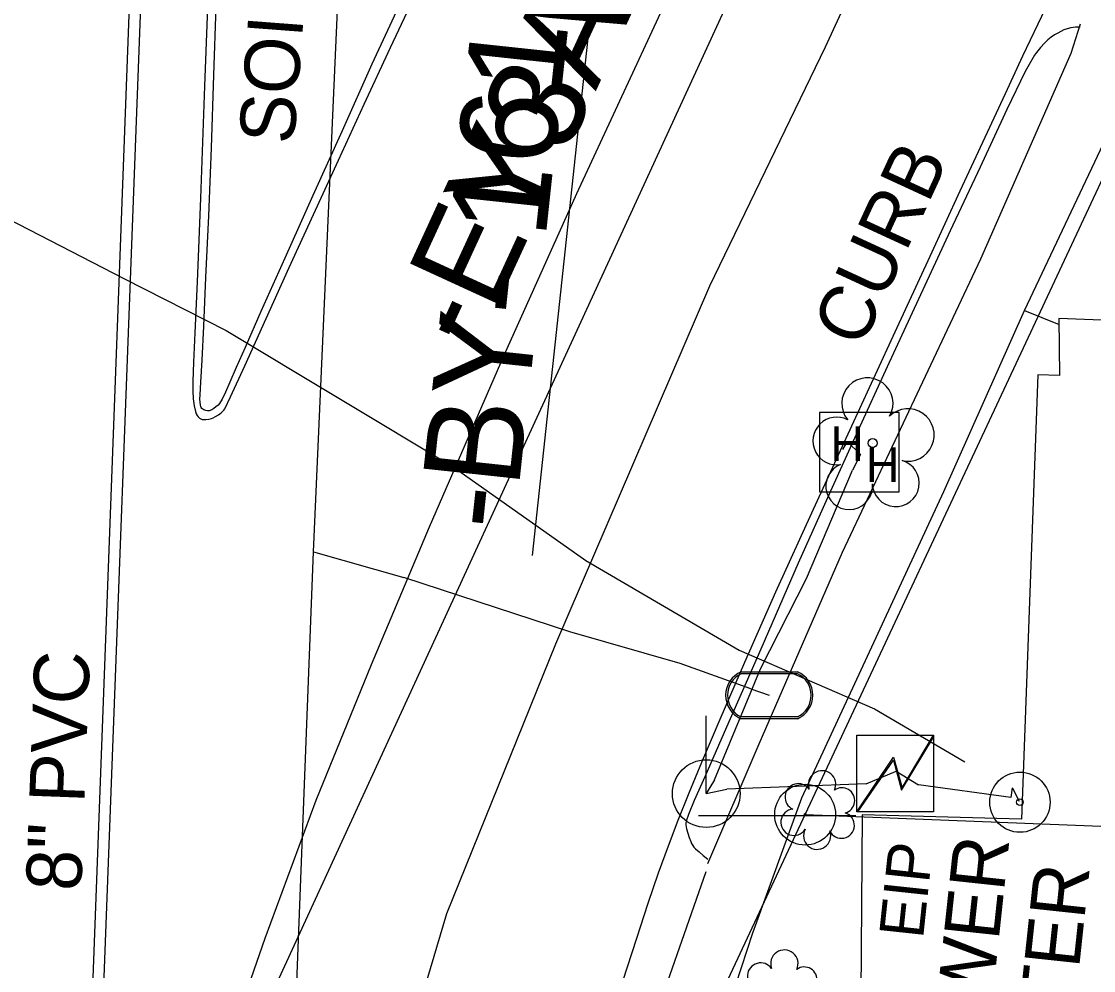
# Model space of a CAD drawing. Extents: x 2100323 to 2109811, y 740376 to 749755.
# Drawn here: x 2105116.4 to 2105194, y 742002.8 to 742071.5 of the extents above; entities that cross this region are included whole.
import ezdxf

# ---------------------------------------------------------------- set-up
doc = ezdxf.new("R2010")
doc.units = 0
for name, color, linetype in [('Exist Building', 7, 'Continuous'), ('Exist Horizontal Alignment', 7, 'Continuous'), ('Exist Horizontal Alignment Direction Label', 7, 'Continuous'), ('Exist Horizontal Baseline Alignment Station Label', 7, 'Continuous'), ('Exist Property Iron Pin CELL', 7, 'Continuous'), ('Exist Property Iron Pin Text', 7, 'Continuous'), ('Exist Property Line', 7, 'Continuous'), ('Exist Right of Way Line', 7, 'Continuous'), ('Exist Roads Curbs', 7, 'Continuous'), ('Exist Roads Curbs Text', 7, 'Continuous'), ('Exist Roads EOP', 7, 'Continuous'), ('Exist Roads EOP Other', 7, 'Continuous'), ('Exist Roads EOP Other Text', 7, 'Continuous'), ('Exist Roads EOT', 7, 'Continuous'), ('Exist Utilities Other Located Object CELL', 7, 'Continuous'), ('Exist Utilities Other Located Object Text', 7, 'Continuous'), ('Exist Utilities Power Hand Hole CELL', 7, 'Continuous'), ('Exist Utilities Power Pole CELL', 7, 'Continuous'), ('Exist Utilities Power Transformer CELL', 7, 'Continuous'), ('Exist Utilities Power UG Cable SUE LOS B', 7, 'Continuous'), ('Exist Utilities Sanitary Sewer UG Line', 7, 'Continuous'), ('Exist Utilities Sanitary Sewer UG Line Text', 7, 'Continuous'), ('Exist Utilities Telephone UG Conduit SUE LOS B', 7, 'Continuous'), ('Exist Utilities TV UG Cable SUE LOS B', 7, 'Continuous'), ('Exist Utilities Water Meter CELL', 7, 'Continuous'), ('Exist Utilities Water UG Line SUE LOS B', 7, 'Continuous'), ('Exist Vegetation Shrub CELL', 7, 'Continuous'), ('Exist Vegetation Tree CELL', 7, 'Continuous')]:
    doc.layers.add(name, color=color, linetype=linetype)

msp = doc.modelspace()

# ---------------------------------------------------------------- linework, layer by layer
at = {"layer": 'Exist Building'}
msp.add_lwpolyline([(2105393.559, 742042.638), (2105393.942, 742090.402), (2105372.247, 742090.309), (2105372.364, 742094.565), (2105338.596, 742094.683), (2105338.145, 742078.613), (2105341.859, 742078.569), (2105341.416, 742009.009), (2105288.421, 742009.568), (2105292.363, 742046.053), (2105191.496, 742049.965), (2105191.549, 742045.846), (2105189.964, 742045.895), (2105188.785, 742013.721), (2105177.253, 742014.042), (2105176.911, 741968.504), (2105222.955, 741968.258), (2105222.207, 741851.808), (2105348.078, 741851.227), (2105349.033, 742009.047), (2105393.054, 742008.763)], dxfattribs=at)
at = {"layer": 'Exist Horizontal Alignment'}
for p, q in [((2105114.07, 741782.467), (2105127.955, 742149.664)), ((2105121.244, 741972.172), (2105202.941, 742149.867))]:
    msp.add_line(p, q, dxfattribs=at)
at = {"layer": 'Exist Horizontal Baseline Alignment Station Label'}
msp.add_line((2105158.033, 742076.269), (2105153.379, 742032.816), dxfattribs=at)
at = {"layer": 'Exist Property Iron Pin CELL'}
for radius in [2.203, 0.0707]:
    msp.add_circle((2105173.125, 742014.049), radius, dxfattribs=at)
at = {"layer": 'Exist Property Line'}
msp.add_line((2105173.125, 742014.049), (2105289.481, 742009.548), dxfattribs=at)
at = {"layer": 'Exist Right of Way Line'}
msp.add_line((2105154.33, 741973.823), (2105222.691, 742120.13), dxfattribs=at)
at = {"layer": 'Exist Roads Curbs'}
for points in [[(2105144.025, 742073.29), (2105141.774, 742068.401), (2105139.603, 742063.573), (2105137.499, 742058.879), (2105135.46, 742054.333), (2105133.738, 742050.485), (2105132.584, 742047.886), (2105131.943, 742046.418), (2105131.489, 742045.373), (2105131.167, 742044.634), (2105130.929, 742044.135), (2105130.725, 742043.809), (2105130.636, 742043.711), (2105130.474, 742043.571), (2105130.324, 742043.455), (2105130.186, 742043.364), (2105130.12, 742043.332), (2105130.056, 742043.308), (2105129.993, 742043.294), (2105129.932, 742043.289), (2105129.87, 742043.291), (2105129.738, 742043.315), (2105129.593, 742043.363), (2105129.523, 742043.401), (2105129.464, 742043.453), (2105129.417, 742043.52), (2105129.382, 742043.601), (2105129.358, 742043.697), (2105129.331, 742043.909), (2105129.324, 742044.133), (2105129.338, 742044.452), (2105129.386, 742045.369), (2105129.471, 742046.968), (2105129.593, 742049.431), (2105129.757, 742052.941), (2105129.954, 742057.41), (2105130.149, 742062.324), (2105130.335, 742067.596), (2105130.506, 742072.573)], [(2105193.026, 742071.079), (2105192.693, 742071.065), (2105192.356, 742071.023), (2105192.099, 742070.957), (2105191.86, 742070.871), (2105191.632, 742070.765), (2105191.406, 742070.642), (2105191.176, 742070.506), (2105190.942, 742070.352), (2105190.697, 742070.153), (2105190.44, 742069.904), (2105190.166, 742069.602), (2105189.871, 742069.248), (2105189.716, 742069.05), (2105189.062, 742067.859), (2105187.73, 742065.104), (2105185.787, 742060.942), (2105183.635, 742056.315), (2105181.34, 742051.381), (2105179.062, 742046.464), (2105176.958, 742041.887), (2105174.957, 742037.483), (2105172.631, 742032.256), (2105169.909, 742026.042), (2105167.437, 742020.373), (2105165.862, 742016.784), (2105165.102, 742015.077), (2105164.679, 742014.07), (2105164.511, 742013.564), (2105164.498, 742013.434), (2105164.498, 742013.298), (2105164.538, 742013.011), (2105164.626, 742012.705), (2105164.73, 742012.402), (2105164.842, 742012.104), (2105164.908, 742011.961), (2105164.988, 742011.825), (2105165.081, 742011.696), (2105165.189, 742011.574), (2105165.444, 742011.346), (2105165.739, 742011.098), (2105166.072, 742010.821)]]:
    msp.add_lwpolyline(points, dxfattribs=at)
at = {"layer": 'Exist Roads EOP'}
for points in [[(2105195.1, 742082.43), (2105193.599, 742079.111), (2105192.261, 742076.186), (2105191.054, 742073.583), (2105189.972, 742071.292), (2105188.869, 742068.964), (2105187.598, 742066.249), (2105186.133, 742063.094), (2105184.323, 742059.185), (2105182.142, 742054.469), (2105179.615, 742048.996), (2105176.768, 742042.817), (2105173.698, 742036.133), (2105170.991, 742030.147), (2105168.744, 742025.059), (2105166.957, 742020.929), (2105165.629, 742017.817), (2105164.71, 742015.61), (2105163.916, 742013.628), (2105163.2, 742011.758), (2105162.495, 742009.812), (2105161.739, 742007.605), (2105160.912, 742005.087), (2105159.909, 742001.961)], [(2105129.963, 742075.061), (2105129.653, 742066.796), (2105129.352, 742058.682), (2105129.116, 742052.622), (2105128.956, 742048.932), (2105128.858, 742046.804), (2105128.808, 742045.425), (2105128.804, 742044.712), (2105128.834, 742044.148), (2105128.897, 742043.648), (2105128.993, 742043.239), (2105129.054, 742043.079), (2105129.123, 742042.948), (2105129.2, 742042.846), (2105129.287, 742042.769), (2105129.384, 742042.711), (2105129.491, 742042.673), (2105129.608, 742042.654), (2105129.735, 742042.655), (2105129.97, 742042.683), (2105130.147, 742042.726), (2105130.278, 742042.786), (2105130.442, 742042.875), (2105130.653, 742042.995), (2105130.765, 742043.066), (2105130.867, 742043.146), (2105130.959, 742043.232), (2105131.041, 742043.327), (2105131.113, 742043.429), (2105131.542, 742044.314), (2105132.56, 742046.544), (2105134.103, 742049.967), (2105135.781, 742053.669), (2105137.529, 742057.497), (2105139.342, 742061.443), (2105141.214, 742065.496), (2105143.12, 742069.606), (2105144.914, 742073.465)]]:
    msp.add_lwpolyline(points, dxfattribs=at)
at = {"layer": 'Exist Roads EOP Other'}
for points in [[(2105188.998, 742050.567), (2105195.555, 742064.436), (2105200.254, 742074.54), (2105206.049, 742087.143), (2105212.074, 742100.512)], [(2105166.081, 742010.498), (2105169.81, 742019.172), (2105175.83, 742033.05), (2105185.844, 742054.299), (2105192.373, 742069.189), (2105193.061, 742071.322)], [(2105164.824, 741991.679), (2105169.348, 742005.482), (2105172.881, 742015.259), (2105183.158, 742037.456), (2105188.998, 742050.567), (2105191.502, 742049.546)], [(2105147.385, 741940.48), (2105150.205, 741954.812), (2105153.355, 741968.426), (2105158.258, 741986.568), (2105161.606, 741997.427), (2105165.959, 742009.922)]]:
    msp.add_lwpolyline(points, dxfattribs=at)
at = {"layer": 'Exist Roads EOT'}
for points in [[(2105182.093, 742112.636), (2105177.783, 742103.921), (2105172.174, 742092.295), (2105168.421, 742084.389), (2105162.799, 742072.415), (2105156.586, 742059.006), (2105151.308, 742047.303), (2105145.911, 742034.869), (2105141.71, 742024.904), (2105137.709, 742015.074), (2105134.028, 742005.078), (2105131.587, 741998.064), (2105129.533, 741992.045), (2105127.985, 741986.696)], [(2105140.512, 741984.365), (2105147.179, 742006.888), (2105155.072, 742026.428), (2105166.228, 742052.345), (2105174.607, 742069.641), (2105183.843, 742089.711), (2105194.629, 742112.742)]]:
    msp.add_lwpolyline(points, dxfattribs=at)
at = {"layer": 'Exist Utilities Other Located Object CELL'}
for radius in [2.18, 0.24]:
    msp.add_circle((2105188.674, 742014.948), radius, dxfattribs=at)
at = {"layer": 'Exist Utilities Power Hand Hole CELL'}
msp.add_line((2105177.122, 742040.138), (2105177.122, 742040.138), dxfattribs=at)
msp.add_lwpolyline([(2105174.172, 742037.413), (2105179.922, 742037.413), (2105179.922, 742043.163), (2105174.172, 742043.163), (2105174.172, 742037.413)], dxfattribs=at)
at = {"layer": 'Exist Utilities Power Pole CELL'}
for q in [(2105165.965, 742021.194), (2105165.965, 742015.569)]:
    msp.add_line((2105165.965, 742015.569), q, dxfattribs=at)
msp.add_circle((2105165.965, 742015.569), 2.45, dxfattribs=at)
at = {"layer": 'Exist Utilities Power Transformer CELL'}
msp.add_line((2105179.717, 742017.201), (2105179.717, 742017.201), dxfattribs=at)
msp.add_lwpolyline([(2105176.873, 742019.812), (2105182.426, 742019.812), (2105182.426, 742014.26), (2105176.873, 742014.26)], close=True, dxfattribs=at)
for points in [[(2105176.873, 742014.26), (2105179.517, 742018.204), (2105180.146, 742015.994), (2105182.426, 742019.812)], [(2105176.943, 742014.26), (2105179.517, 742017.994), (2105180.104, 742015.812), (2105182.426, 742019.658)]]:
    msp.add_lwpolyline(points, dxfattribs=at)
at = {"layer": 'Exist Utilities Power UG Cable SUE LOS B'}
for p, q in [((2105176.174, 742041.072), (2105175.819, 742040.483)), ((2105177.55, 742016.281), (2105167.45, 742015.882)), ((2105188.649, 742014.992), (2105188.169, 742015.931))]:
    msp.add_line(p, q, dxfattribs=at)
for points in [[(2105176.174, 742041.072), (2105177.122, 742040.138), (2105176.548, 742038.995)], [(2105166.554, 742016.578), (2105169.895, 742024.614), (2105173.232, 742031.155), (2105176.548, 742038.995)], [(2105177.55, 742016.281), (2105179.717, 742017.201), (2105181.322, 742016.2)], [(2105166.554, 742016.578), (2105165.964, 742015.567), (2105167.45, 742015.882)], [(2105188.169, 742015.931), (2105188.119, 742015.982), (2105188.009, 742015.298), (2105181.322, 742016.2)]]:
    msp.add_lwpolyline(points, dxfattribs=at)
at = {"layer": 'Exist Utilities Sanitary Sewer UG Line'}
msp.add_lwpolyline([(2105125.925, 742119.115), (2105107.923, 741637.482)], dxfattribs=at)
at = {"layer": 'Exist Utilities Telephone UG Conduit SUE LOS B'}
msp.add_line((2105165.416, 742013.994), (2105176.788, 742013.991), dxfattribs=at)
at = {"layer": 'Exist Utilities TV UG Cable SUE LOS B'}
msp.add_lwpolyline([(2105095.616, 742068.707), (2105106.868, 742061.496), (2105114.626, 742057.599), (2105123.819, 742052.878), (2105131.224, 742049.114), (2105147.642, 742039.226), (2105157.25, 742032.452), (2105168.344, 742025.96), (2105178.147, 742021.704), (2105184.683, 742017.872)], dxfattribs=at)
at = {"layer": 'Exist Utilities Water Meter CELL'}
msp.add_line((2105170.534, 742022.694), (2105170.534, 742022.694), dxfattribs=at)
for points in [[(2105168.496, 742024.394), (2105172.572, 742024.394)], [(2105168.496, 742024.257), (2105172.572, 742024.257)], [(2105172.572, 742021.132), (2105168.471, 742021.132)], [(2105172.572, 742020.994), (2105168.471, 742020.994)]]:
    msp.add_lwpolyline(points, dxfattribs=at)
for centre, radius, start, end in [((2105169.227, 742022.689), 1.855, 113.17804, 245.97939), ((2105169.238, 742022.688), 1.735, 115.30093, 243.78236), ((2105171.827, 742022.695), 1.856, 293.64832, 66.30838), ((2105171.839, 742022.694), 1.726, 295.12717, 64.87283)]:
    msp.add_arc(centre, radius, start, end, dxfattribs=at)
at = {"layer": 'Exist Utilities Water UG Line SUE LOS B'}
msp.add_line((2105169.188, 742023.15), (2105170.534, 742022.694), dxfattribs=at)
for points in [[(2105121.485, 741679.881), (2105122.261, 741701.679), (2105123.534, 741730.099), (2105127.235, 741791.303), (2105130.345, 741851.732), (2105134.568, 741956.374), (2105137.545, 742033.083), (2105141.408, 742120.3), (2105141.648, 742144.896), (2105141.764, 742148.567), (2105142.227, 742156.512), (2105142.292, 742165.064)], [(2105137.545, 742033.083), (2105144.075, 742031.23)], [(2105169.188, 742023.15), (2105164.085, 742024.983), (2105156.095, 742027.292), (2105144.075, 742031.23)]]:
    msp.add_lwpolyline(points, dxfattribs=at)
at = {"layer": 'Exist Vegetation Shrub CELL'}
msp.add_line((2105174.119, 742014.199), (2105174.119, 742014.199), dxfattribs=at)
for centre, radius, start, end in [((2105174.348, 742016.24), 0.99, 334.83907, 200.47174), ((2105172.636, 742015.326), 0.968, 35.89076, 245.42165), ((2105175.791, 742015.068), 0.929, 284.45672, 126.08612), ((2105172.319, 742013.495), 0.955, 95.10992, 327.95341), ((2105175.756, 742013.27), 0.937, 204.99133, 73.46012), ((2105173.991, 742012.516), 0.984, 151.27966, 21.38702), ((2105171.621, 742003.261), 0.99, 334.83907, 200.47174), ((2105169.91, 742002.347), 0.968, 35.89076, 245.42165), ((2105173.064, 742002.089), 0.929, 284.45672, 126.08612)]:
    msp.add_arc(centre, radius, start, end, dxfattribs=at)
at = {"layer": 'Exist Vegetation Tree CELL'}
msp.add_line((2105178.017, 742040.953), (2105178.017, 742040.953), dxfattribs=at)
msp.add_circle((2105178.017, 742040.953), 0.326, dxfattribs=at)
for centre, radius, start, end in [((2105177.632, 742043.826), 1.856, 330.16508, 219.71335), ((2105180.566, 742041.541), 1.899, 257.1011, 134.19993), ((2105175.411, 742041.106), 1.727, 62.66361, 279.3457), ((2105176.313, 742037.832), 1.689, 111.56708, 6.23104), ((2105179.69, 742038.053), 1.698, 181.28216, 74.55999)]:
    msp.add_arc(centre, radius, start, end, dxfattribs=at)

# ---------------------------------------------------------------- texts
at = {"layer": 'Exist Horizontal Alignment Direction Label'}
msp.add_text('-EY3A-', height=7, rotation=65.30889, dxfattribs=at).set_placement((2105149.273, 742047.501))
at = {"layer": 'Exist Horizontal Baseline Alignment Station Label'}
msp.add_text('-BY- 161    ', height=7, rotation=83.88645, dxfattribs=at).set_placement((2105152.059, 742034.495))
at = {"layer": 'Exist Property Iron Pin Text'}
msp.add_text('EIP', height=3.2, rotation=83.88645, dxfattribs=at).set_placement((2105181.655, 742005.002))
at = {"layer": 'Exist Roads Curbs Text'}
msp.add_text('CURB', height=4, rotation=65.24665, dxfattribs=at).set_placement((2105177.18, 742047.706))
at = {"layer": 'Exist Roads EOP Other Text'}
msp.add_text('SOIL', height=4, rotation=85.65529, dxfattribs=at).set_placement((2105136.124, 742062.537))
at = {"layer": 'Exist Utilities Other Located Object Text'}
for s, p in [('POWER', (2105185.77, 741992.169)), ('METER', (2105191.746, 741991.624))]:
    msp.add_text(s, height=4, rotation=83.88645, dxfattribs=at).set_placement(p)
at = {"layer": 'Exist Utilities Power Hand Hole CELL'}
for p in [(2105174.963, 742039.664), (2105177.527, 742038.144)]:
    msp.add_text('H', height=2.5, dxfattribs=at).set_placement(p)
at = {"layer": 'Exist Utilities Sanitary Sewer UG Line Text'}
msp.add_text('8" PVC', height=4, rotation=87.85945, dxfattribs=at).set_placement((2105120.716, 742008.477))

doc.saveas('drawing.dxf')
